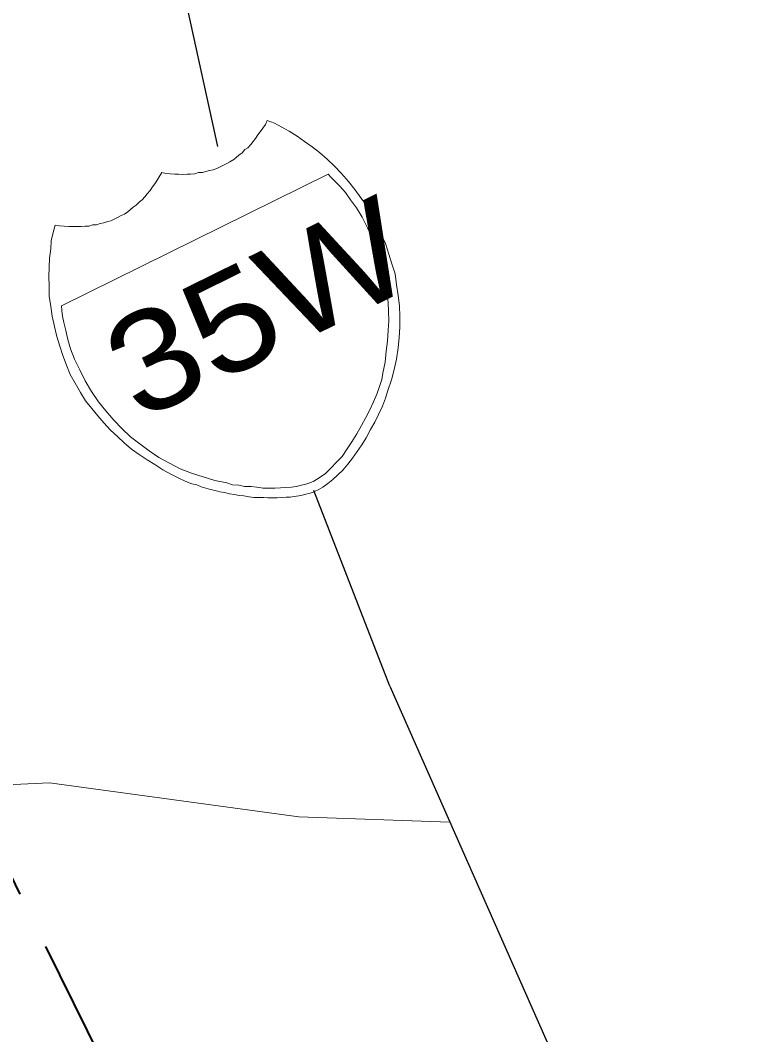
# Model space of a CAD drawing. Extents: x 2356606 to 2371222, y 6973096 to 6982644.
# Drawn here: x 2370841.6 to 2370878.4, y 6980470.1 to 6980522 of the extents above; entities that cross this region are included whole.
import ezdxf

# ---------------------------------------------------------------- set-up
doc = ezdxf.new("R2010")
doc.units = 0
doc.header["$LTSCALE"] = 2
doc.linetypes.add('LONG_DASHED', pattern=[7.5, 6, -1.5])
doc.layers.add('62', color=7, linetype='Continuous', lineweight=13)
doc.layers.add('63', color=7, linetype='Continuous', lineweight=13)

msp = doc.modelspace()

# ---------------------------------------------------------------- linework, layer by layer
at = {"layer": '62', "lineweight": 25}
for p, q in [((2370849.412, 6980526.103), (2370851.721, 6980515.578)), ((2370860.544, 6980487.937), (2370856.653, 6980497.96))]:
    msp.add_line(p, q, dxfattribs=at)
at = {"layer": '62'}
for points in [[(2370849.732, 6980514.166), (2370849.945, 6980514.146), (2370850.166, 6980514.154), (2370850.337, 6980514.161), (2370850.558, 6980514.169), (2370850.748, 6980514.241), (2370850.949, 6980514.24), (2370851.121, 6980514.298), (2370851.322, 6980514.346), (2370851.503, 6980514.386), (2370851.696, 6980514.457), (2370851.858, 6980514.536), (2370852.039, 6980514.626), (2370852.2, 6980514.706), (2370852.361, 6980514.785), (2370852.552, 6980514.905), (2370852.675, 6980515.014), (2370852.816, 6980515.134), (2370852.988, 6980515.246), (2370853.129, 6980515.416), (2370853.284, 6980515.515), (2370853.424, 6980515.687), (2370853.555, 6980515.827), (2370853.677, 6980515.988), (2370853.791, 6980516.169), (2370853.912, 6980516.329), (2370854.042, 6980516.518), (2370854.173, 6980516.71), (2370854.274, 6980516.911), (2370854.647, 6980516.765), (2370855.02, 6980516.575), (2370855.4, 6980516.361), (2370855.802, 6980516.106), (2370856.183, 6980515.841), (2370856.574, 6980515.559), (2370856.944, 6980515.266), (2370857.337, 6980514.931), (2370857.726, 6980514.548), (2370858.076, 6980514.193), (2370858.425, 6980513.789), (2370858.756, 6980513.376), (2370859.066, 6980512.951), (2370859.365, 6980512.547), (2370859.614, 6980512.093), (2370859.884, 6980511.649), (2370860.093, 6980511.123), (2370860.322, 6980510.609), (2370860.49, 6980510.065), (2370860.657, 6980509.572), (2370860.816, 6980509.047), (2370860.893, 6980508.484), (2370860.983, 6980507.949), (2370861.05, 6980507.407), (2370861.067, 6980506.862), (2370861.055, 6980506.33), (2370861.02, 6980505.786), (2370860.977, 6980505.263), (2370860.883, 6980504.69), (2370860.769, 6980504.157), (2370860.626, 6980503.633), (2370860.454, 6980503.074), (2370860.321, 6980502.68), (2370860.167, 6980502.278), (2370859.974, 6980501.855), (2370859.788, 6980501.464), (2370859.555, 6980501.073), (2370859.332, 6980500.662), (2370859.108, 6980500.302), (2370858.876, 6980499.959), (2370858.642, 6980499.619), (2370858.399, 6980499.298), (2370858.148, 6980498.998), (2370857.873, 6980498.737), (2370857.63, 6980498.516), (2370857.378, 6980498.317), (2370857.125, 6980498.119), (2370856.884, 6980497.997)], [(2370856.884, 6980497.997), (2370856.723, 6980497.918), (2370856.58, 6980497.85), (2370856.401, 6980497.81), (2370856.248, 6980497.76), (2370856.066, 6980497.721), (2370855.885, 6980497.681), (2370855.655, 6980497.641), (2370855.443, 6980497.614), (2370855.24, 6980497.614), (2370855.019, 6980497.605), (2370854.778, 6980497.587), (2370854.556, 6980497.577), (2370854.307, 6980497.58), (2370854.094, 6980497.6), (2370853.841, 6980497.602), (2370853.592, 6980497.604), (2370853.35, 6980497.634), (2370853.079, 6980497.676), (2370852.836, 6980497.708), (2370852.586, 6980497.758), (2370852.344, 6980497.788), (2370852.081, 6980497.859), (2370851.84, 6980497.893), (2370851.609, 6980497.953), (2370851.358, 6980498.006), (2370851.127, 6980498.067), (2370850.886, 6980498.148), (2370850.666, 6980498.242), (2370850.414, 6980498.292), (2370850.192, 6980498.384), (2370850.002, 6980498.466), (2370849.771, 6980498.577), (2370849.369, 6980498.781), (2370848.929, 6980499.014), (2370848.518, 6980499.29), (2370848.123, 6980499.521), (2370847.713, 6980499.796), (2370847.325, 6980500.08), (2370846.943, 6980500.393), (2370846.602, 6980500.728), (2370846.242, 6980501.051), (2370845.91, 6980501.416), (2370845.602, 6980501.787), (2370845.292, 6980502.163), (2370844.972, 6980502.556), (2370844.712, 6980502.98), (2370844.433, 6980503.446), (2370844.183, 6980503.899), (2370843.995, 6980504.384), (2370843.807, 6980504.867), (2370843.649, 6980505.342), (2370843.499, 6980505.846), (2370843.37, 6980506.359), (2370843.264, 6980506.882), (2370843.196, 6980507.377), (2370843.107, 6980507.909), (2370843.1, 6980508.433), (2370843.091, 6980508.904), (2370843.106, 6980509.388), (2370843.127, 6980509.852), (2370843.191, 6980510.333), (2370843.214, 6980510.748), (2370843.304, 6980511.17), (2370843.417, 6980511.551), (2370843.64, 6980511.511), (2370843.871, 6980511.498), (2370844.102, 6980511.487), (2370844.304, 6980511.485), (2370844.534, 6980511.475), (2370844.735, 6980511.474), (2370844.947, 6980511.501), (2370845.149, 6980511.5), (2370845.32, 6980511.56), (2370845.522, 6980511.561), (2370845.713, 6980511.63), (2370845.895, 6980511.67), (2370846.115, 6980511.728), (2370846.269, 6980511.778), (2370846.43, 6980511.858), (2370846.632, 6980511.956), (2370846.791, 6980512.035), (2370846.955, 6980512.116), (2370847.127, 6980512.227), (2370847.267, 6980512.345), (2370847.408, 6980512.467), (2370847.559, 6980512.567), (2370847.725, 6980512.747), (2370847.874, 6980512.847), (2370847.995, 6980513.007), (2370848.128, 6980513.146), (2370848.269, 6980513.316), (2370848.4, 6980513.508), (2370848.521, 6980513.668), (2370848.635, 6980513.849), (2370848.744, 6980514.03), (2370848.866, 6980514.243), (2370849.088, 6980514.2), (2370849.299, 6980514.176), (2370849.532, 6980514.165), (2370849.732, 6980514.166)], [(2370809.285, 6980486.6), (2370810.526, 6980485.306), (2370818.332, 6980484.791), (2370828.717, 6980482.314), (2370843.121, 6980482.975), (2370855.891, 6980481.246), (2370863.629, 6980480.974)]]:
    msp.add_lwpolyline(points, dxfattribs=at)
msp.add_lwpolyline([(2370857.392, 6980514.155), (2370843.73, 6980507.414), (2370843.75, 6980507.172), (2370843.786, 6980506.891), (2370843.847, 6980506.568), (2370843.953, 6980506.145), (2370844.054, 6980505.692), (2370844.19, 6980505.208), (2370844.398, 6980504.684), (2370844.668, 6980504.137), (2370844.946, 6980503.572), (2370845.266, 6980503.029), (2370845.625, 6980502.504), (2370846.004, 6980502.039), (2370846.414, 6980501.565), (2370846.825, 6980501.14), (2370847.265, 6980500.704), (2370847.746, 6980500.339), (2370848.218, 6980499.993), (2370848.72, 6980499.64), (2370849.262, 6980499.356), (2370849.805, 6980499.07), (2370850.395, 6980498.836), (2370850.988, 6980498.65), (2370851.582, 6980498.468), (2370852.196, 6980498.345), (2370852.497, 6980498.243), (2370852.809, 6980498.221), (2370853.111, 6980498.169), (2370853.443, 6980498.156), (2370853.736, 6980498.125), (2370854.056, 6980498.084), (2370854.36, 6980498.083), (2370854.66, 6980498.08), (2370854.952, 6980498.098), (2370855.224, 6980498.108), (2370855.516, 6980498.127), (2370855.746, 6980498.165), (2370856.019, 6980498.224), (2370856.242, 6980498.282), (2370856.46, 6980498.341), (2370856.665, 6980498.442), (2370856.934, 6980498.601), (2370857.249, 6980498.831), (2370857.521, 6980499.092), (2370857.816, 6980499.412), (2370858.099, 6980499.703), (2370858.364, 6980500.084), (2370858.608, 6980500.456), (2370858.861, 6980500.856), (2370859.106, 6980501.278), (2370859.327, 6980501.688), (2370859.532, 6980502.09), (2370859.705, 6980502.503), (2370859.887, 6980502.894), (2370860.022, 6980503.286), (2370860.145, 6980503.646), (2370860.187, 6980503.968), (2370860.31, 6980504.532), (2370860.363, 6980505.085), (2370860.434, 6980505.6), (2370860.458, 6980506.161), (2370860.492, 6980506.654), (2370860.483, 6980507.127), (2370860.455, 6980507.59), (2370860.398, 6980508.064), (2370860.341, 6980508.536), (2370860.282, 6980508.959), (2370860.163, 6980509.402), (2370860.037, 6980509.817), (2370859.906, 6980510.23), (2370859.759, 6980510.633), (2370859.588, 6980511.025), (2370859.399, 6980511.407), (2370859.13, 6980511.952), (2370858.843, 6980512.44), (2370858.542, 6980512.842), (2370858.282, 6980513.215), (2370857.992, 6980513.549), (2370857.751, 6980513.783), (2370857.551, 6980513.986)], close=True, dxfattribs=at)
at = {"layer": '62', "linetype": 'LONG_DASHED', "lineweight": 40}
msp.add_lwpolyline([(2370677.388, 6980417.215), (2370705.629, 6980359.988), (2370861.529, 6980436.93), (2370833.286, 6980494.155), (2370677.105, 6980417.075)], dxfattribs=at)
at = {"layer": '62', "lineweight": 25}
msp.add_lwpolyline([(2370860.544, 6980487.937), (2370878.798, 6980446.631), (2370885.051, 6980438.124)], dxfattribs=at)
at = {"layer": '63', "lineweight": 25}
for p, q in [((2370849.412, 6980526.103), (2370851.721, 6980515.578)), ((2370860.544, 6980487.937), (2370856.653, 6980497.96))]:
    msp.add_line(p, q, dxfattribs=at)
at = {"layer": '63'}
for points in [[(2370849.732, 6980514.166), (2370849.945, 6980514.146), (2370850.166, 6980514.154), (2370850.337, 6980514.161), (2370850.558, 6980514.169), (2370850.748, 6980514.241), (2370850.949, 6980514.24), (2370851.121, 6980514.298), (2370851.322, 6980514.346), (2370851.503, 6980514.386), (2370851.696, 6980514.457), (2370851.858, 6980514.536), (2370852.039, 6980514.626), (2370852.2, 6980514.706), (2370852.361, 6980514.785), (2370852.552, 6980514.905), (2370852.675, 6980515.014), (2370852.816, 6980515.134), (2370852.988, 6980515.246), (2370853.129, 6980515.416), (2370853.284, 6980515.515), (2370853.424, 6980515.687), (2370853.555, 6980515.827), (2370853.677, 6980515.988), (2370853.791, 6980516.169), (2370853.912, 6980516.329), (2370854.042, 6980516.518), (2370854.173, 6980516.71), (2370854.274, 6980516.911), (2370854.647, 6980516.765), (2370855.02, 6980516.575), (2370855.4, 6980516.361), (2370855.802, 6980516.106), (2370856.183, 6980515.841), (2370856.574, 6980515.559), (2370856.944, 6980515.266), (2370857.337, 6980514.931), (2370857.726, 6980514.548), (2370858.076, 6980514.193), (2370858.425, 6980513.789), (2370858.756, 6980513.376), (2370859.066, 6980512.951), (2370859.365, 6980512.547), (2370859.614, 6980512.093), (2370859.884, 6980511.649), (2370860.093, 6980511.123), (2370860.322, 6980510.609), (2370860.49, 6980510.065), (2370860.657, 6980509.572), (2370860.816, 6980509.047), (2370860.893, 6980508.484), (2370860.983, 6980507.949), (2370861.05, 6980507.407), (2370861.067, 6980506.862), (2370861.055, 6980506.33), (2370861.02, 6980505.786), (2370860.977, 6980505.263), (2370860.883, 6980504.69), (2370860.769, 6980504.157), (2370860.626, 6980503.633), (2370860.454, 6980503.074), (2370860.321, 6980502.68), (2370860.167, 6980502.278), (2370859.974, 6980501.855), (2370859.788, 6980501.464), (2370859.555, 6980501.073), (2370859.332, 6980500.662), (2370859.108, 6980500.302), (2370858.876, 6980499.959), (2370858.642, 6980499.619), (2370858.399, 6980499.298), (2370858.148, 6980498.998), (2370857.873, 6980498.737), (2370857.63, 6980498.516), (2370857.378, 6980498.317), (2370857.125, 6980498.119), (2370856.884, 6980497.997)], [(2370856.884, 6980497.997), (2370856.723, 6980497.918), (2370856.58, 6980497.85), (2370856.401, 6980497.81), (2370856.248, 6980497.76), (2370856.066, 6980497.721), (2370855.885, 6980497.681), (2370855.655, 6980497.641), (2370855.443, 6980497.614), (2370855.24, 6980497.614), (2370855.019, 6980497.605), (2370854.778, 6980497.587), (2370854.556, 6980497.577), (2370854.307, 6980497.58), (2370854.094, 6980497.6), (2370853.841, 6980497.602), (2370853.592, 6980497.604), (2370853.35, 6980497.634), (2370853.079, 6980497.676), (2370852.836, 6980497.708), (2370852.586, 6980497.758), (2370852.344, 6980497.788), (2370852.081, 6980497.859), (2370851.84, 6980497.893), (2370851.609, 6980497.953), (2370851.358, 6980498.006), (2370851.127, 6980498.067), (2370850.886, 6980498.148), (2370850.666, 6980498.242), (2370850.414, 6980498.292), (2370850.192, 6980498.384), (2370850.002, 6980498.466), (2370849.771, 6980498.577), (2370849.369, 6980498.781), (2370848.929, 6980499.014), (2370848.518, 6980499.29), (2370848.123, 6980499.521), (2370847.713, 6980499.796), (2370847.325, 6980500.08), (2370846.943, 6980500.393), (2370846.602, 6980500.728), (2370846.242, 6980501.051), (2370845.91, 6980501.416), (2370845.602, 6980501.787), (2370845.292, 6980502.163), (2370844.972, 6980502.556), (2370844.712, 6980502.98), (2370844.433, 6980503.446), (2370844.183, 6980503.899), (2370843.995, 6980504.384), (2370843.807, 6980504.867), (2370843.649, 6980505.342), (2370843.499, 6980505.846), (2370843.37, 6980506.359), (2370843.264, 6980506.882), (2370843.196, 6980507.377), (2370843.107, 6980507.909), (2370843.1, 6980508.433), (2370843.091, 6980508.904), (2370843.106, 6980509.388), (2370843.127, 6980509.852), (2370843.191, 6980510.333), (2370843.214, 6980510.748), (2370843.304, 6980511.17), (2370843.417, 6980511.551), (2370843.64, 6980511.511), (2370843.871, 6980511.498), (2370844.102, 6980511.487), (2370844.304, 6980511.485), (2370844.534, 6980511.475), (2370844.735, 6980511.474), (2370844.947, 6980511.501), (2370845.149, 6980511.5), (2370845.32, 6980511.56), (2370845.522, 6980511.561), (2370845.713, 6980511.63), (2370845.895, 6980511.67), (2370846.115, 6980511.728), (2370846.269, 6980511.778), (2370846.43, 6980511.858), (2370846.632, 6980511.956), (2370846.791, 6980512.035), (2370846.955, 6980512.116), (2370847.127, 6980512.227), (2370847.267, 6980512.345), (2370847.408, 6980512.467), (2370847.559, 6980512.567), (2370847.725, 6980512.747), (2370847.874, 6980512.847), (2370847.995, 6980513.007), (2370848.128, 6980513.146), (2370848.269, 6980513.316), (2370848.4, 6980513.508), (2370848.521, 6980513.668), (2370848.635, 6980513.849), (2370848.744, 6980514.03), (2370848.866, 6980514.243), (2370849.088, 6980514.2), (2370849.299, 6980514.176), (2370849.532, 6980514.165), (2370849.732, 6980514.166)], [(2370809.285, 6980486.6), (2370810.526, 6980485.306), (2370818.332, 6980484.791), (2370828.717, 6980482.314), (2370843.121, 6980482.975), (2370855.891, 6980481.246), (2370863.629, 6980480.974)]]:
    msp.add_lwpolyline(points, dxfattribs=at)
msp.add_lwpolyline([(2370857.392, 6980514.155), (2370843.73, 6980507.414), (2370843.75, 6980507.172), (2370843.786, 6980506.891), (2370843.847, 6980506.568), (2370843.953, 6980506.145), (2370844.054, 6980505.692), (2370844.19, 6980505.208), (2370844.398, 6980504.684), (2370844.668, 6980504.137), (2370844.946, 6980503.572), (2370845.266, 6980503.029), (2370845.625, 6980502.504), (2370846.004, 6980502.039), (2370846.414, 6980501.565), (2370846.825, 6980501.14), (2370847.265, 6980500.704), (2370847.746, 6980500.339), (2370848.218, 6980499.993), (2370848.72, 6980499.64), (2370849.262, 6980499.356), (2370849.805, 6980499.07), (2370850.395, 6980498.836), (2370850.988, 6980498.65), (2370851.582, 6980498.468), (2370852.196, 6980498.345), (2370852.497, 6980498.243), (2370852.809, 6980498.221), (2370853.111, 6980498.169), (2370853.443, 6980498.156), (2370853.736, 6980498.125), (2370854.056, 6980498.084), (2370854.36, 6980498.083), (2370854.66, 6980498.08), (2370854.952, 6980498.098), (2370855.224, 6980498.108), (2370855.516, 6980498.127), (2370855.746, 6980498.165), (2370856.019, 6980498.224), (2370856.242, 6980498.282), (2370856.46, 6980498.341), (2370856.665, 6980498.442), (2370856.934, 6980498.601), (2370857.249, 6980498.831), (2370857.521, 6980499.092), (2370857.816, 6980499.412), (2370858.099, 6980499.703), (2370858.364, 6980500.084), (2370858.608, 6980500.456), (2370858.861, 6980500.856), (2370859.106, 6980501.278), (2370859.327, 6980501.688), (2370859.532, 6980502.09), (2370859.705, 6980502.503), (2370859.887, 6980502.894), (2370860.022, 6980503.286), (2370860.145, 6980503.646), (2370860.187, 6980503.968), (2370860.31, 6980504.532), (2370860.363, 6980505.085), (2370860.434, 6980505.6), (2370860.458, 6980506.161), (2370860.492, 6980506.654), (2370860.483, 6980507.127), (2370860.455, 6980507.59), (2370860.398, 6980508.064), (2370860.341, 6980508.536), (2370860.282, 6980508.959), (2370860.163, 6980509.402), (2370860.037, 6980509.817), (2370859.906, 6980510.23), (2370859.759, 6980510.633), (2370859.588, 6980511.025), (2370859.399, 6980511.407), (2370859.13, 6980511.952), (2370858.843, 6980512.44), (2370858.542, 6980512.842), (2370858.282, 6980513.215), (2370857.992, 6980513.549), (2370857.751, 6980513.783), (2370857.551, 6980513.986)], close=True, dxfattribs=at)
at = {"layer": '63', "linetype": 'LONG_DASHED', "lineweight": 40}
msp.add_lwpolyline([(2370677.388, 6980417.215), (2370705.629, 6980359.988), (2370861.529, 6980436.93), (2370833.286, 6980494.155), (2370677.105, 6980417.075)], dxfattribs=at)
at = {"layer": '63', "lineweight": 25}
msp.add_lwpolyline([(2370860.544, 6980487.937), (2370878.798, 6980446.631), (2370885.051, 6980438.124)], dxfattribs=at)

# ---------------------------------------------------------------- texts
at = {"layer": '62', "width": 1.15}
msp.add_text('35W', height=5.099, rotation=26.268, dxfattribs=at).set_placement((2370847.694, 6980501.468))
at = {"layer": '63', "width": 1.15}
msp.add_text('35W', height=5.099, rotation=26.268, dxfattribs=at).set_placement((2370847.694, 6980501.468))

doc.saveas('drawing.dxf')
